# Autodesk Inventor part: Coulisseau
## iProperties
Author: Flavien MARTY
Shininess: 20.0
PropertySet Name: _Private Model Information
Created: 2001-10
Part Number: Coulisseau
Material: Par défaut
Document SubType Name: Modélisation
Designer: Flavien MARTY
Control State: 0
Master: False
Checked Out: False
PropertySet Name: Design Tracking Control
Density: 0.0
Volumn: 0.0
Area: 0.0
PropertySet Name: Model Information
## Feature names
1. Base1
